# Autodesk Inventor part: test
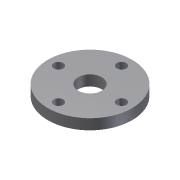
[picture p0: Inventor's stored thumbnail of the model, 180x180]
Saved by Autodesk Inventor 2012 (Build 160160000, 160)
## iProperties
Shininess: 65.0
Angle Display Precision: 2
Document Length Units: 11269
Document Angle Units: 11279
Document Time Units: 11290
Document Mass Units: 11283
Document Length Units Precision: 3
Document Angle Units Precision: 2
Created: 2002-02
Part Number: test
Document SubType Name: Modeling
Designer: ***
Density: 1 g/cm^3
Material: Default
Density: 0.0
Volumn: 0.0
Area: 0.0
PropertySet Name: Model Information
Control State: 0
Master: False
Checked Out: False
Author: ***
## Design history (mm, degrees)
sketch "Sketch1"
  geometry: C1 r 100 at (0, 0); C2 r 28 at (0, 0)
  constraints: 2 centre point, 1 coincident
  dimensions: "d0" = 200 diameter of C1; "d1" = 56 diameter of C2
extrude "Extrusion1" new body sketch "Sketch1" stored distance "d2" = 25; taper "d3" = 0 deg
sketch "Sketch2"
  geometry: 2 further points
  dimensions: "d4" = 75 distance of point (0, 0) point (-75, 0)
hole "Hole1" sketch "Sketch2" at (-75, 0) diameter "d5" = 22.3; stored, may be unused: countersink angle "d9" = 82 deg, drill point angle "d11" = 118 deg; dims "d6" = 6, "d7" = 4, "d8" = 2, "d10" = 8
pattern_circular "Circular Pattern1" dims angle "d14" = 360 deg
body "Solid1"
